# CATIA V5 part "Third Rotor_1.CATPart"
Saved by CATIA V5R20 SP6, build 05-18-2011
Part number: Third Rotor
Bounding box of the stored display mesh (mm): x -33.695 to 8.913, y -23.761 to 23.762, z -30 to 8.5
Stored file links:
  E:\#01 CATIA Lecture Materials\#06 DMU\#04 DMU Page01 KIN EX04\Third Rotor_1.CATPart
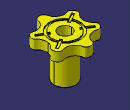
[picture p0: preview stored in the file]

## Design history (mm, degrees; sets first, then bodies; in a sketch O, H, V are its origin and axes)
Set1
  Line1 "Third Rotor Axis": stored without definition
  Extract1: ExtractElem face of Solid1
  Boundary1 "Outer Boundary.1": Boundary edge of Extract1
Body1 (main body)
Body2 "Third Rotor"
  Solid1: solid without history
